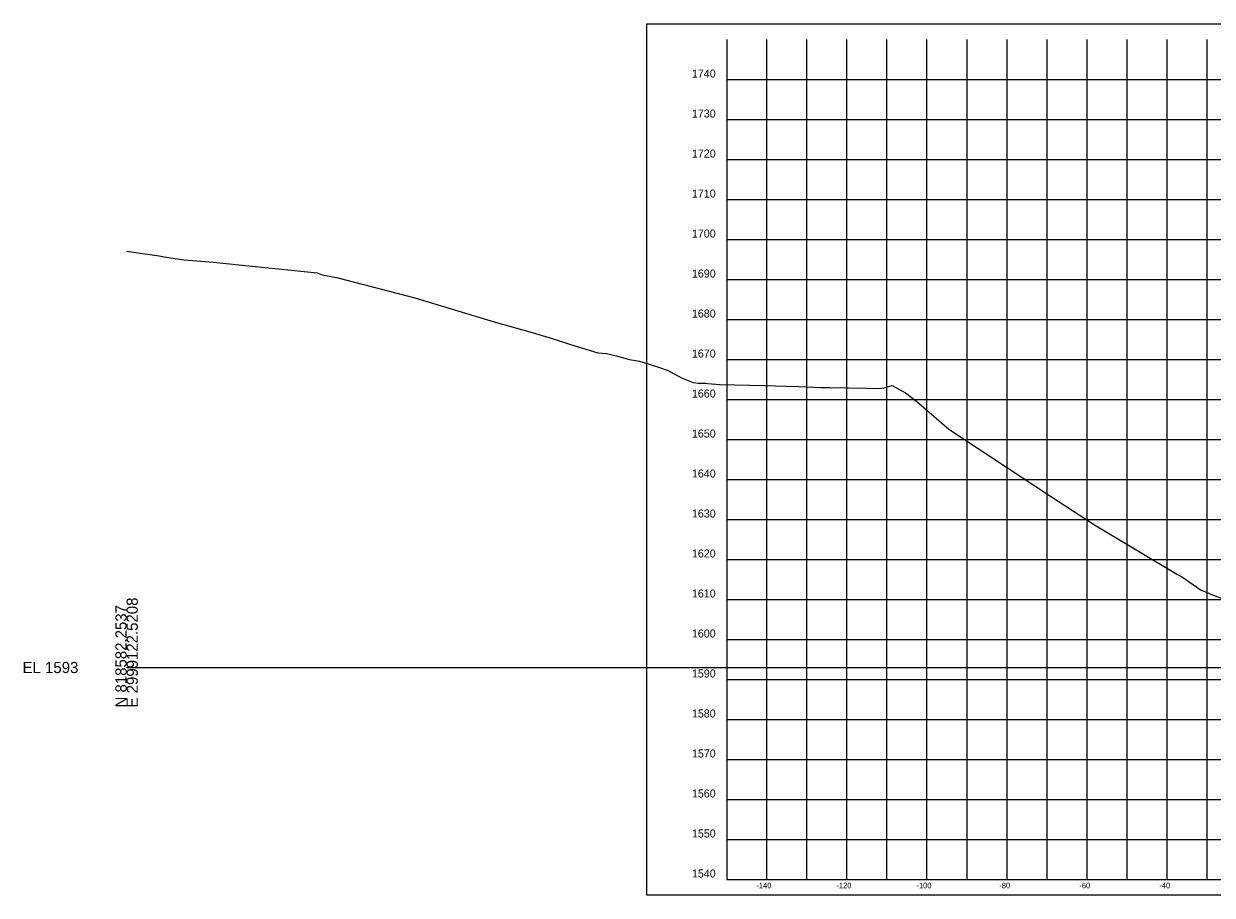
# Model space of a CAD drawing. Extents: x -26 to 1067, y -71 to 1837.
# Drawn here: x -25.7 to 271.3, y 443.1 to 660.9 of the extents above; entities that cross this region are included whole.
import ezdxf

# ---------------------------------------------------------------- set-up
doc = ezdxf.new("R2010")
doc.units = 0
for name, color, linetype in [('DESIGN - SHEET - Corner Text', 7, 'Continuous'), ('DESIGN - SHEET - Light Grid', 7, 'Continuous'), ('DESIGN - SHEET - Linework', 7, 'Continuous'), ('DESIGN - SHEET - Plot Shape', 7, 'Continuous'), ('SURVEY - GROUND - Top of Ground', 7, 'Continuous')]:
    doc.layers.add(name, color=color, linetype=linetype)

msp = doc.modelspace()

# ---------------------------------------------------------------- linework, layer by layer
at = {"layer": 'DESIGN - SHEET - Light Grid'}
msp.add_line((0, 500), (300, 500), dxfattribs=at)
at = {"layer": 'DESIGN - SHEET - Linework'}
for p, q in [((160, 447), (160, 657)), ((170, 447), (170, 657)), ((180, 447), (180, 657)), ((190, 447), (190, 657)), ((200, 447), (200, 657)), ((210, 447), (210, 657)), ((220, 447), (220, 657)), ((230, 447), (230, 657)), ((240, 447), (240, 657)), ((250, 447), (250, 657)), ((260, 447), (260, 657)), ((270, 447), (270, 657)), ((150, 647), (450, 647)), ((150, 637), (450, 637)), ((150, 627), (450, 627)), ((150, 617), (450, 617)), ((150, 607), (450, 607)), ((150, 597), (450, 597)), ((150, 587), (450, 587)), ((150, 577), (450, 577)), ((150, 567), (450, 567)), ((150, 557), (450, 557)), ((150, 547), (450, 547)), ((150, 537), (450, 537)), ((150, 527), (450, 527)), ((150, 517), (450, 517)), ((150, 507), (450, 507)), ((150, 497), (450, 497)), ((150, 487), (450, 487)), ((150, 477), (450, 477)), ((150, 467), (450, 467)), ((150, 457), (450, 457))]:
    msp.add_line(p, q, dxfattribs=at)
msp.add_lwpolyline([(150, 657), (150, 447), (450, 447), (450, 657)], dxfattribs=at)
at = {"layer": 'DESIGN - SHEET - Plot Shape'}
msp.add_lwpolyline([(130, 660.94), (470, 660.94), (470, 443.06), (130, 443.06)], close=True, dxfattribs=at)
at = {"layer": 'SURVEY - GROUND - Top of Ground'}
msp.add_lwpolyline([(0, 604.06), (8.14, 602.95), (9.35, 602.71), (14.42, 601.89), (21.67, 601.32), (47.62, 598.68), (48.91, 598.15), (52.79, 597.38), (72.03, 592.41), (91.82, 586.41), (101.35, 583.77), (106.35, 582.24), (110.65, 580.83), (117.76, 578.7), (119.93, 578.46), (122.43, 577.88), (125.02, 577.2), (125.67, 577.04), (128.17, 576.59), (130.09, 575.96), (131.36, 575.59), (133.39, 574.88), (134.81, 574.41), (135.14, 574.32), (138.68, 572.44), (141.57, 571.28), (142.83, 571.06), (144.7, 571.08), (145.18, 571.04), (148.24, 570.76), (159.46, 570.5), (164.81, 570.37), (167.99, 570.25), (173.42, 570.04), (175.77, 570.02), (185, 569.8), (187.93, 569.77), (189.29, 569.95), (191.26, 570.47), (192.81, 569.69), (194.59, 568.66), (197.47, 566.51), (205.45, 559.55), (230.86, 542.8), (239.9, 536.93), (241.88, 535.67), (262.57, 523.22), (263.58, 522.73), (268.53, 519.3), (270.24, 518.65), (270.82, 518.37), (274.79, 516.94)], dxfattribs=at)

# ---------------------------------------------------------------- texts
at = {"layer": 'DESIGN - SHEET - Corner Text'}
for s, height, p in [('1740', 2, (141.25, 647.5)), ('1730', 2, (141.25, 637.5)), ('1720', 2, (141.25, 627.5)), ('1710', 2, (141.25, 617.5)), ('1700', 2, (141.25, 607.5)), ('1690', 2, (141.25, 597.5)), ('1680', 2, (141.25, 587.5)), ('1670', 2, (141.25, 577.5)), ('1660', 2, (141.25, 567.5)), ('1650', 2, (141.25, 557.5)), ('1640', 2, (141.25, 547.5)), ('1630', 2, (141.25, 537.5)), ('1620', 2, (141.25, 527.5)), ('1610', 2, (141.25, 517.5)), ('1600', 2, (141.25, 507.5)), ('1590', 2, (141.25, 497.5)), ('1580', 2, (141.25, 487.5)), ('1570', 2, (141.25, 477.5)), ('1560', 2, (141.25, 467.5)), ('1550', 2, (141.25, 457.5)), ('1540', 2, (141.25, 447.5)), ('-140', 1.4, (157.37, 444.8)), ('-120', 1.4, (177.37, 444.8)), ('-100', 1.4, (197.37, 444.8)), ('-80', 1.4, (218.06, 444.8)), ('-60', 1.4, (238.06, 444.8)), ('-40', 1.4, (258.06, 444.8))]:
    msp.add_text(s, height=height, dxfattribs=at).set_placement(p)
at = {"layer": 'DESIGN - SHEET - Light Grid'}
for s, p in [('E 2999122.5208', (2.8, 490)), ('N 818582.2537', (0, 490))]:
    msp.add_text(s, height=2.8, rotation=90, dxfattribs=at).set_placement(p)
msp.add_text('EL 1593', height=2.8, dxfattribs=at).set_placement((-26, 498.6))

doc.saveas('drawing.dxf')
